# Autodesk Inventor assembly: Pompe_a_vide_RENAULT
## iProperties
Shininess: 64.0
Length Units: 11269
Angle Units: 11279
Time Units: 11290
Mass Units: 11283
Length Display Precision: 3
Angle Display Precision: 2
Compacted: True
Created: 2005-01
Part Number: Pompe_a_vide_RENAULT
Document SubType Name: Assembly
Designer: Flavien MARTY
Density: 0.0
Volumn: 0.0
Area: 0.0
PropertySet Name: Model Information
Control State: 0
Master: False
Checked Out: False
Author: Flavien MARTY
